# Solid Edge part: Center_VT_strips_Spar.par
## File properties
Author: haileyy
Template: ansi part.par
Last saved by: haileyy
Revision: 9
Application: Solid Edge
Accuracy: 0.990
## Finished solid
Body 1: solid body, 6 faces, 12 edges, 8 vertices.
  Faces by surface: plane 6
  Edges by curve: line 12
Bounding box of the edges (mm): 6.477 x 3.302 x 234.950, from (-90.6392, 15.9453, -234.95) to (-84.1622, 19.2473, 0).
Planar faces by outward normal: +x 1, +y 1, +z 1, -x 1, -y 1, -z 1
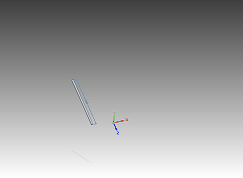
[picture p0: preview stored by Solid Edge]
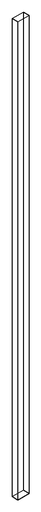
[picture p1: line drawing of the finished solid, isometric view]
